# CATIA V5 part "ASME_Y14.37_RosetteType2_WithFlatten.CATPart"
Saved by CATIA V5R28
Part number: 333X3333-303
Revision: --
Nomenclature: ASME_Y14.37_RosetteType2
Bounding box of the stored display mesh (mm): x -183.371 to 149.821, y -702.181 to 651.972, z 2.54 to 93.98
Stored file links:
  C:\Users\jvl2147\Documents\ASME Y14.37\PartExamples\ASME_Y14.37_RosetteType2_WithFlatten.CATPart
  \\NW\Data\MSE-Composites\ASME Y14.37\ASME Y-14.37_COMPOSITES.CATMaterial
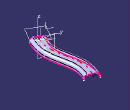
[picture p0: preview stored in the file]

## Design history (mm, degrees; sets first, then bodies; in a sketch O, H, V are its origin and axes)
AxisSystem1 "ROSETTE COORDINATE SYSTEM": origin (-72.9205, -637.9645, 93.98), X (0.5026, 0.8645, 0), Y (-0.8645, 0.5026, 0), Z (0, 0, 1)
CompParametersFeature1 "CATCoParametersFeatName": Value 0, Value 45, Value -45, Value 90
CompEOPGroupFeature1 "CATCoEOPGroupFeatName"
CompStacking1 "Stacking"
CompIsoThickAreasGroup1 "CATCoIsoThickAreasGroupFeatName": RefAddThickness 0
TTRSSet1
f4a2d38f3ddc11d3a929006094b99c4b_11 "CATTPSSet"
CompReviewTools1 "Review tools"
Set1 "CONSTRUCTION GEOMETRY"
  Set2 "CONSTRUCTION - LAMINATE REFERENCE SURFACE"
    Sketch1 on xy-plane, origin (0, 0, 0), H (1, 0, 0), V (0, 1, 0)
      spline S1 through (-79.505, -649.09) (21.2912, -260.3998) (-51.6257, 228.8061) (37.963, 602.845)
    Plane1: type Normal, Curve Sketch1, RefPoint vertex of Sketch1, Ratio 0
    Sketch2 on Plane1, origin (-464.3095, -417.3341, 0), H (-0.8566, 0.5159, 0), V (0, 0, 1)
      line L1 (-525.4052, 91.6386) -> (-373.0052, 91.6386)
      line L2 (-322.2052, 40.8386) -> (-322.2052, 0)
      line L3 (-576.2052, 0) -> (-576.2052, 40.8386)
      reference projected point E1 (-449.2052, 0) from vertex of Sketch1
      reference projected point E2 (-449.2052, 0) from vertex of Sketch1
      arc A1 centre (-373.0052, 40.8386) radius 50.8 from (-373.0052, 91.6386) to (-322.2052, 40.8386) cw
      arc A2 centre (-525.4052, 40.8386) radius 50.8 from (-576.2052, 40.8386) to (-525.4052, 91.6386) cw
      distance E1 L2 = 127
      distance E2 L3 = 127
      radius A1 = 50.8
      radius A2 = 50.8
      horizontal: L1 H
      vertical: L2 V, L3 V
      tangency: A1 L1, A1 L2, A2 L3, A2 L1
    Sweep1: type Unspec, Profile Sketch2, Guide Sketch1
  Set3 "CONSTRUCTION - PLIES EOPS"
    Plane2: type Normal, Curve Sketch1, RefPoint vertex of Sketch1, Ratio 0
    Plane3: type Normal, Curve Sketch1, RefPoint {point type OnCurve, Support Sketch1, Length 1118.262}, Ratio 0.99
    Plane4: type Normal, Curve Sketch1, Ratio 0.01
    Intersect1: ToIntersect1 Plane3, ToIntersect2 Sweep1
    Intersect2: ToIntersect1 Sweep1, ToIntersect2 Plane4
    Plane5: type Offset, RefPlane xy-plane, Offset 2.54
    Intersect3: ToIntersect1 Plane5, ToIntersect2 Join1
    Near1: MultiElement Intersect3, ReferenceElement edge of Sweep1
    Near2: MultiElement Intersect3, ReferenceElement edge of Sweep1
  Set4 "CONSTRUCTION - ROSETTE COORDINATE SYSTEM"
    Intersect4: ToIntersect1 Plane4, ToIntersect2 Project2
    Line1: type Tangency, RefPoint Intersect4, Curve Project2, Start 0, End 25.4
    Plane6: type Offset, RefPlane xy-plane, Offset 93.98
    Project1 "PROJECT": ToProject Sketch1, Support Join1, Direction xy-plane
  Set5 "CONSTRUCTION - ROSETTE TRANSFORMS"
    Line2 "Ply.1_Rosette_transfer_X": type Tangency, RefPoint {point type OnCurve, Support Project2, Length 288.56}, Curve Project2, Support Join1, Start 0, End 25.4
    Line3 "Ply.1_Rosette_transfer_X.Renamed": type Tangency, RefPoint {point type OnCurve, Support Project2, Length 536.186}, Curve Project2, Support Join1, Start 25.4, End 0
    Line4 "Ply.1_Rosette_transfer_X.Renamed": type Tangency, RefPoint {point type OnCurve, Support Project2, Length 783.62}, Curve Project2, Support Join1, Start 25.4, End 0
    Line5 "Ply.1_Rosette_transfer_X.Renamed": type Tangency, RefPoint {point type OnCurve, Support Project2, Length 1274.71}, Curve Project2, Support Join1, Start 25.4, End 0
    Line6 "Ply.1_Rosette_transfer_X.Renamed": type Tangency, RefPoint {point type OnCurve, Support Project2, Length 1017.245}, Curve Project2, Support Join1, Start 25.4, End 0
    AxisSystem2 "ROSETTE COORDINATE SYSTEM": origin (16.8931, -379.3831, 93.98), X (0.1242, 0.9923, 0), Y (-0.9923, 0.1242, 0), Z (0, 0, 1)
    AxisSystem3 "ROSETTE COORDINATE SYSTEM.Renamed": origin (7.1166, -132.8437, 93.98), X (-0.1632, 0.9866, 0), Y (-0.9866, -0.1632, 0), Z (0, 0, 1)
    AxisSystem4 "ROSETTE COORDINATE SYSTEM.Renamed1": origin (-38.9217, 110.2518, 93.98), X (-0.1571, 0.9876, 0), Y (-0.9876, -0.1571, 0), Z (0, 0, 1)
    AxisSystem5 "ROSETTE COORDINATE SYSTEM.Renamed2": origin (29.3229, 586.9432, 93.98), X (0.4677, 0.8839, 0), Y (-0.8839, 0.4677, 0), Z (0, 0, 1)
    AxisSystem6 "ROSETTE COORDINATE SYSTEM.Renamed3": origin (-47.995, 342.9553, 93.98), X (0.1137, 0.9935, 0), Y (-0.9935, 0.1137, 0), Z (0, 0, 1)
    Point1: type OnSurface, Support Join1, Length 362.156, Direction (-0.4364, -0.3881, 0.8118)
    Line7: type Normal, RefPoint Point1, RefSkin Join1, Start 254, End 0
  Plane7: type Offset, RefPlane YZ plane of AxisSystem2, Offset 0
Set6 "ENGINEERING GEOMETRY"
  Set7 "LAMINATE REFERENCE SURFACE"
    Join1 "LAMINATE REFERENCE SURFACE": Elements Sweep1
  Set8 "GUIDE CURVE - ZERO DEGREE ORIENTATION"
    Project2 "GUIDE CURVE - 0°": ToProject Sketch1, Support Plane6
  Plane8 "Flatten Plane": type Offset, RefPlane XY plane of AxisSystem1, Offset 50.8
Body1 (main body)
Body2 "-303"
  CompIsoThickAreasSolid1 "Area Solid.1": IsoAreasGroup CompIsoThickAreasGroup1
